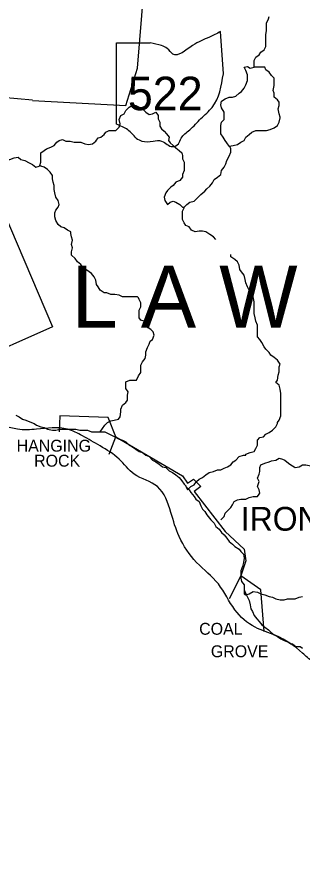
# Model space of a CAD drawing. Extents: x 0 to 34, y 0 to 22.
# Drawn here: x 6.907 to 7.373, y 14.971 to 16.352 of the extents above; entities that cross this region are included whole.
import ezdxf

# ---------------------------------------------------------------- set-up
doc = ezdxf.new("R2010")
doc.units = 0
doc.layers.add('Default', color=7, linetype='Continuous')
doc.layers.add('TR_Turning_Path1', color=7, linetype='Continuous')

msp = doc.modelspace()

# ---------------------------------------------------------------- linework, layer by layer
at = {"layer": 'Default'}
msp.add_line((7.0847, 16.207), (7.0847, 16.207), dxfattribs=at)
for points in [[(7.1038, 16.2683), (7.1256, 16.5342)], [(7.2947, 16.2697), (7.2947, 16.2765), (7.2947, 16.2806), (7.2974, 16.286), (7.3029, 16.2901), (7.3056, 16.2942), (7.3111, 16.2983), (7.3138, 16.3038), (7.3138, 16.3106), (7.3138, 16.3174), (7.3138, 16.3229), (7.3151, 16.3297), (7.3151, 16.3351), (7.3151, 16.3419), (7.3179, 16.3488), (7.3192, 16.3528)], [(7.2444, 16.2591), (7.2398, 16.3281)], [(7.0696, 16.1763), (7.0696, 16.3097), (7.1248, 16.3097)], [(7.0847, 16.207), (7.1038, 16.2683), (7.1038, 16.2683)], [(7.2538, 16.1402), (7.2497, 16.1456), (7.247, 16.1497), (7.2442, 16.1552), (7.2402, 16.1606), (7.2402, 16.1661), (7.2402, 16.1742), (7.2415, 16.1797), (7.2456, 16.1838), (7.2456, 16.1906), (7.2456, 16.1961), (7.2415, 16.2029), (7.2402, 16.2083), (7.2415, 16.2138), (7.247, 16.2179), (7.2538, 16.2206), (7.2592, 16.2206), (7.2647, 16.222), (7.2701, 16.2274), (7.2742, 16.2301), (7.2783, 16.2356), (7.2811, 16.241), (7.2838, 16.2479), (7.2838, 16.2533), (7.2838, 16.2574), (7.2811, 16.2642), (7.2783, 16.2697), (7.2838, 16.271), (7.2879, 16.2683), (7.2947, 16.2697), (7.2947, 16.2697)], [(7.337, 16.1879), (7.3356, 16.1933), (7.3342, 16.2015), (7.3356, 16.207), (7.3356, 16.2124), (7.3329, 16.2165), (7.3274, 16.2206), (7.3274, 16.2274), (7.326, 16.2315), (7.3274, 16.2397), (7.3274, 16.2451), (7.3274, 16.252), (7.3233, 16.256), (7.3192, 16.2615), (7.3138, 16.2656), (7.3124, 16.2697), (7.307, 16.2697), (7.3029, 16.2697), (7.2961, 16.2697), (7.2947, 16.2697), (7.2947, 16.2697)], [(6.8829, 16.2206), (6.872, 16.0611), (6.9647, 15.8443), (6.6948, 15.7243)], [(6.8829, 16.2206), (6.932, 16.2165), (6.932, 16.2165)], [(6.932, 16.2151), (7.0847, 16.207)], [(7.0902, 16.2042), (7.0943, 16.207), (7.1011, 16.207), (7.1065, 16.2042), (7.112, 16.2015), (7.1174, 16.1961), (7.1229, 16.192), (7.1284, 16.1933), (7.1338, 16.1961), (7.1379, 16.1906), (7.1379, 16.1851), (7.1406, 16.1797), (7.1406, 16.1729), (7.1433, 16.1688), (7.1474, 16.1647), (7.1515, 16.1606), (7.1556, 16.1552), (7.1543, 16.1497), (7.157, 16.1456), (7.1624, 16.1415), (7.1665, 16.1374), (7.172, 16.1333), (7.1761, 16.1292), (7.1774, 16.1252), (7.1774, 16.1252)], [(7.0111, 16.147), (7.0179, 16.1442), (7.0234, 16.1429), (7.0302, 16.1442), (7.0356, 16.1483), (7.0397, 16.1538), (7.0438, 16.1552), (7.0493, 16.1592), (7.052, 16.1633), (7.0575, 16.1661), (7.0629, 16.1661), (7.0684, 16.1661), (7.0738, 16.1715), (7.0752, 16.177), (7.0738, 16.1838), (7.0765, 16.1906), (7.082, 16.1933), (7.0847, 16.1988), (7.0902, 16.2042), (7.0902, 16.2042), (7.0902, 16.2042)], [(7.2538, 16.1402), (7.2606, 16.1415), (7.2674, 16.1429), (7.2729, 16.147), (7.2783, 16.1497), (7.2811, 16.1552), (7.2865, 16.1592), (7.2906, 16.1633), (7.2974, 16.1661), (7.3029, 16.1661), (7.3097, 16.1661), (7.3151, 16.1661), (7.3206, 16.1674), (7.3274, 16.1702), (7.3329, 16.1742), (7.3356, 16.1797), (7.337, 16.1865), (7.337, 16.1879)], [(6.9443, 16.1088), (6.9457, 16.1143), (6.9457, 16.1211), (6.9457, 16.1292), (6.9511, 16.1333), (6.9552, 16.1361), (6.962, 16.1388), (6.9675, 16.1415), (6.9716, 16.147), (6.9756, 16.1497), (6.9811, 16.1511), (6.9866, 16.1483), (6.9934, 16.1483), (7.0002, 16.147), (7.007, 16.147), (7.0097, 16.147), (7.0111, 16.147)], [(7.1802, 16.0406), (7.1843, 16.0447), (7.1897, 16.0488), (7.1965, 16.0502), (7.2006, 16.0543), (7.2047, 16.0584), (7.2074, 16.0611), (7.2142, 16.0665), (7.217, 16.0706), (7.2224, 16.0747), (7.2265, 16.0802), (7.2292, 16.0856), (7.2347, 16.0897), (7.2402, 16.0938), (7.2415, 16.1006), (7.2456, 16.1061), (7.2483, 16.1115), (7.2497, 16.117), (7.2538, 16.1238), (7.2565, 16.1306), (7.2565, 16.1361), (7.2552, 16.1388), (7.2538, 16.1402)], [(7.1774, 16.1252), (7.1774, 16.1197), (7.1802, 16.1143), (7.1802, 16.1061), (7.1802, 16.1006), (7.1774, 16.0938), (7.1774, 16.0897), (7.1733, 16.0843), (7.1665, 16.0815), (7.1624, 16.0761), (7.1583, 16.0733), (7.1529, 16.0679), (7.1502, 16.0638), (7.1474, 16.057), (7.1488, 16.0515), (7.1529, 16.0447), (7.157, 16.0488), (7.1624, 16.0502), (7.1665, 16.0488), (7.1733, 16.0447), (7.1774, 16.0406), (7.1802, 16.0406)], [(6.8775, 16.1183), (6.8829, 16.117), (6.8884, 16.1183), (6.8952, 16.1183), (6.902, 16.1211), (6.9088, 16.1224), (6.9129, 16.1183), (6.9197, 16.117), (6.9266, 16.1129), (6.932, 16.1102), (6.9375, 16.1061), (6.9429, 16.1074), (6.9443, 16.1088)], [(6.9947, 15.9997), (6.9893, 16.0025), (6.9838, 16.0065), (6.9784, 16.0079), (6.9743, 16.012), (6.9702, 16.0188), (6.9688, 16.0243), (6.9688, 16.0311), (6.9702, 16.0352), (6.9743, 16.0406), (6.9756, 16.0447), (6.9743, 16.0515), (6.9702, 16.057), (6.9688, 16.0638), (6.9675, 16.0693), (6.9675, 16.0761), (6.9661, 16.0815), (6.9647, 16.087), (6.9647, 16.0924), (6.9607, 16.0979), (6.9566, 16.102), (6.9511, 16.1061), (6.9457, 16.1074), (6.9443, 16.1088)], [(7.232, 15.9875), (7.2279, 15.9915), (7.2224, 15.9956), (7.2156, 15.9997), (7.2102, 16.0011), (7.2047, 16.0011), (7.1979, 15.9997), (7.1924, 16.0025), (7.1883, 16.0079), (7.1829, 16.0106), (7.1802, 16.0147), (7.1774, 16.0202), (7.1774, 16.027), (7.1774, 16.0338), (7.1802, 16.0393), (7.1802, 16.0406)], [(7.1038, 15.8934), (7.0984, 15.8934), (7.0915, 15.8934), (7.0847, 15.8934), (7.0793, 15.8934), (7.0738, 15.8961), (7.067, 15.8975), (7.0602, 15.8975), (7.0534, 15.9002), (7.0493, 15.9002), (7.0425, 15.9043), (7.0397, 15.9097), (7.037, 15.9138), (7.0356, 15.9206), (7.0329, 15.9261), (7.0288, 15.9316), (7.0247, 15.9343), (7.0193, 15.9384), (7.0138, 15.9425), (7.0111, 15.9466), (7.0056, 15.9506), (7.0016, 15.9561), (6.9961, 15.9615), (6.9961, 15.967), (6.9975, 15.9738), (6.9961, 15.9793), (6.9975, 15.9861), (6.9961, 15.9915), (6.9947, 15.997), (6.9947, 15.9997)], [(7.292, 15.8934), (7.2906, 15.9002), (7.2865, 15.9043), (7.2838, 15.9097), (7.2811, 15.9166), (7.2797, 15.922), (7.2783, 15.9288), (7.2742, 15.9343), (7.2715, 15.9384), (7.2701, 15.9452), (7.2674, 15.9506), (7.2633, 15.9547), (7.2565, 15.9588), (7.2565, 15.9629)], [(7.1284, 15.8238), (7.1311, 15.8307), (7.1297, 15.8361), (7.1256, 15.8402), (7.1215, 15.8429), (7.1174, 15.847), (7.1147, 15.8538), (7.1093, 15.8552), (7.1065, 15.8593), (7.1065, 15.8647), (7.1065, 15.8716), (7.1093, 15.877), (7.1093, 15.8838), (7.1065, 15.8893), (7.1052, 15.892), (7.1038, 15.8934)], [(7.337, 15.742), (7.3356, 15.7489), (7.3301, 15.7529), (7.3329, 15.757), (7.3342, 15.7652), (7.3356, 15.7707), (7.3356, 15.7788), (7.337, 15.7829), (7.3329, 15.7898), (7.3274, 15.7938), (7.322, 15.7979), (7.3192, 15.802), (7.3138, 15.8075), (7.3111, 15.8116), (7.307, 15.8184), (7.3042, 15.8238), (7.3001, 15.8279), (7.3001, 15.8347), (7.3001, 15.8416), (7.3001, 15.847), (7.2974, 15.8538), (7.2961, 15.8593), (7.2947, 15.8661), (7.2947, 15.8729), (7.2947, 15.8797), (7.2947, 15.8852), (7.2933, 15.8934), (7.292, 15.8934)], [(7.0874, 15.7257), (7.0874, 15.7325), (7.0888, 15.7379), (7.0847, 15.7434), (7.0847, 15.7489), (7.0847, 15.7543), (7.0915, 15.757), (7.0984, 15.757), (7.1024, 15.757), (7.1052, 15.7639), (7.1093, 15.7693), (7.1093, 15.7748), (7.1093, 15.7816), (7.112, 15.787), (7.1161, 15.7925), (7.1174, 15.7979), (7.1174, 15.8034), (7.1202, 15.8102), (7.1229, 15.8157), (7.1243, 15.8211), (7.1284, 15.8238), (7.1284, 15.8238)], [(7.3329, 15.6875), (7.3356, 15.6916), (7.3383, 15.6984), (7.3383, 15.7052), (7.3383, 15.7107), (7.3383, 15.7161), (7.3383, 15.7243), (7.3383, 15.7298), (7.3383, 15.7352), (7.337, 15.742), (7.337, 15.742)], [(7.3329, 15.6875), (7.3356, 15.6916), (7.3383, 15.6984), (7.3383, 15.7052), (7.3383, 15.7107), (7.3383, 15.7161), (7.3383, 15.7243), (7.3383, 15.7298), (7.3383, 15.7352), (7.337, 15.742), (7.337, 15.742)], [(7.037, 15.6725), (7.0425, 15.6725), (7.0465, 15.678), (7.0506, 15.6834), (7.0547, 15.6875), (7.0602, 15.6902), (7.0656, 15.6916), (7.0725, 15.693), (7.0752, 15.697), (7.0765, 15.7052), (7.0765, 15.7093), (7.0793, 15.7161), (7.0847, 15.7202), (7.0874, 15.7243), (7.0874, 15.7257)], [(6.9048, 15.6998), (6.9102, 15.697), (6.9157, 15.693), (6.9211, 15.6916), (6.9279, 15.6889), (6.9347, 15.6861), (6.9388, 15.6834), (6.9457, 15.6807), (6.9511, 15.6793), (6.9566, 15.6766), (6.9647, 15.6752), (6.9702, 15.6752), (6.977, 15.6766), (6.9838, 15.6766), (6.9893, 15.6766), (6.9961, 15.6766), (7.0029, 15.6766), (7.0097, 15.6752), (7.0166, 15.6752), (7.022, 15.6752), (7.0288, 15.6725), (7.0356, 15.6725), (7.037, 15.6725)], [(7.0575, 15.6357), (7.0684, 15.6643), (7.0561, 15.6957), (6.977, 15.6984), (6.9756, 15.6725)], [(7.2811, 15.6357), (7.2879, 15.6384), (7.2947, 15.6398), (7.2974, 15.6452), (7.3001, 15.6507), (7.3001, 15.6589), (7.3042, 15.663), (7.3097, 15.6643), (7.3138, 15.6684), (7.3192, 15.6711), (7.3247, 15.6752), (7.3301, 15.6807), (7.3329, 15.6861), (7.3329, 15.6875)], [(7.2811, 15.6357), (7.2879, 15.6384), (7.2947, 15.6398), (7.2974, 15.6452), (7.3001, 15.6507), (7.3001, 15.6589), (7.3042, 15.663), (7.3097, 15.6643), (7.3138, 15.6684), (7.3192, 15.6711), (7.3247, 15.6752), (7.3301, 15.6807), (7.3329, 15.6861), (7.3329, 15.6875)], [(7.037, 15.6725), (7.0438, 15.6725), (7.0506, 15.6725), (7.0561, 15.6698), (7.0615, 15.667), (7.067, 15.6643), (7.0738, 15.6602), (7.0793, 15.6589), (7.0847, 15.6561), (7.0902, 15.6507), (7.0943, 15.648), (7.1011, 15.6439), (7.1065, 15.6398), (7.112, 15.6384), (7.1174, 15.6343), (7.1229, 15.6316), (7.1284, 15.6261), (7.1338, 15.6234), (7.1393, 15.6193), (7.1447, 15.6152), (7.1502, 15.6139), (7.1556, 15.6084), (7.1611, 15.6057), (7.1665, 15.6016), (7.172, 15.5975), (7.1761, 15.5921), (7.1802, 15.5866), (7.1829, 15.5839), (7.1829, 15.5839), (7.1829, 15.5825)], [(7.3615, 15.6139), (7.3683, 15.6152), (7.3738, 15.618), (7.3792, 15.618), (7.3874, 15.6166), (7.3942, 15.6152), (7.3983, 15.618), (7.4038, 15.6221), (7.4092, 15.6261), (7.4133, 15.6316), (7.4188, 15.6343), (7.4256, 15.6384), (7.4283, 15.6425), (7.4351, 15.6466), (7.4378, 15.6507), (7.4419, 15.6561), (7.4447, 15.663), (7.4474, 15.667), (7.4474, 15.6684)], [(7.0684, 15.6643), (7.1774, 15.6002), (7.1856, 15.588), (7.1952, 15.5948), (7.2074, 15.5825), (7.1965, 15.5743), (7.247, 15.5089), (7.2783, 15.4803), (7.2811, 15.4612), (7.2729, 15.4366)], [(7.1829, 15.5825), (7.1856, 15.5771), (7.1911, 15.5825), (7.1965, 15.5852), (7.2006, 15.5907), (7.2047, 15.5948), (7.2102, 15.5975), (7.2156, 15.6016), (7.2211, 15.6057), (7.2279, 15.6071), (7.2347, 15.6098), (7.2402, 15.6098), (7.2456, 15.6125), (7.2511, 15.6152), (7.2565, 15.618), (7.2606, 15.6234), (7.2647, 15.6261), (7.2701, 15.6316), (7.277, 15.6343), (7.2811, 15.6343), (7.2811, 15.6357)], [(7.1829, 15.5825), (7.1856, 15.5771), (7.1911, 15.5825), (7.1965, 15.5852), (7.2006, 15.5907), (7.2047, 15.5948), (7.2102, 15.5975), (7.2156, 15.6016), (7.2211, 15.6057), (7.2279, 15.6071), (7.2347, 15.6098), (7.2402, 15.6098), (7.2456, 15.6125), (7.2511, 15.6152), (7.2565, 15.618), (7.2606, 15.6234), (7.2647, 15.6261), (7.2701, 15.6316), (7.277, 15.6343), (7.2811, 15.6343), (7.2811, 15.6357)], [(7.3042, 15.5716), (7.3029, 15.5771), (7.3001, 15.5825), (7.3029, 15.5907), (7.3001, 15.5962), (7.3029, 15.603), (7.3042, 15.6071), (7.3042, 15.6139), (7.3056, 15.618), (7.3124, 15.6207), (7.3192, 15.6234), (7.3233, 15.6248), (7.3301, 15.6261), (7.3356, 15.6289), (7.341, 15.6275), (7.3451, 15.6261), (7.3506, 15.6207), (7.3547, 15.618), (7.3601, 15.6152), (7.3615, 15.6139), (7.3615, 15.6139)], [(7.1829, 15.5825), (7.1883, 15.5771), (7.1911, 15.573), (7.1965, 15.5662), (7.1993, 15.5621), (7.2047, 15.558), (7.2074, 15.5512), (7.2102, 15.5457), (7.2142, 15.5416), (7.217, 15.5362), (7.2238, 15.528), (7.2238, 15.528)], [(7.2402, 15.528), (7.2456, 15.5334), (7.247, 15.5389), (7.2511, 15.543), (7.2565, 15.5484), (7.2592, 15.5525), (7.262, 15.558), (7.2674, 15.5607), (7.2729, 15.5621), (7.2811, 15.5621), (7.2865, 15.5648), (7.2933, 15.5662), (7.3001, 15.5662), (7.3029, 15.5702), (7.3042, 15.5716)], [(7.2238, 15.528), (7.2292, 15.5225), (7.232, 15.5171), (7.2374, 15.513), (7.2415, 15.5075), (7.2456, 15.5034), (7.2497, 15.498), (7.2538, 15.4925), (7.2592, 15.4884), (7.2633, 15.4844), (7.2701, 15.4803), (7.2729, 15.4762), (7.277, 15.4721), (7.2783, 15.4653), (7.277, 15.4584), (7.2756, 15.4516), (7.2729, 15.4448), (7.2729, 15.4394), (7.2729, 15.4325), (7.2742, 15.4271), (7.2783, 15.4216), (7.2783, 15.4135), (7.2783, 15.4135)], [(7.3111, 15.3453), (7.3056, 15.4135), (7.2729, 15.4366), (7.2538, 15.3985)], [(7.2783, 15.4135), (7.2811, 15.4066), (7.2838, 15.4012), (7.2865, 15.3957), (7.2879, 15.3889), (7.2892, 15.3821), (7.292, 15.378), (7.2947, 15.3712), (7.2988, 15.3657), (7.3029, 15.3616), (7.307, 15.3562), (7.3124, 15.3521), (7.3179, 15.348), (7.322, 15.3439), (7.3274, 15.3398), (7.3329, 15.3371), (7.3383, 15.333), (7.3438, 15.3303), (7.3506, 15.3276), (7.3547, 15.3248), (7.3574, 15.3248)], [(7.2783, 15.4135), (7.2783, 15.4066), (7.2811, 15.4053), (7.2865, 15.4066), (7.2933, 15.4107), (7.3001, 15.4094), (7.3056, 15.4066), (7.3124, 15.4053), (7.3192, 15.4025), (7.3247, 15.4012), (7.3301, 15.3985), (7.337, 15.3971), (7.3438, 15.3971), (7.3492, 15.3985), (7.3547, 15.3985), (7.3615, 15.3985), (7.3683, 15.4012), (7.3738, 15.4025)], [(7.3574, 15.3248), (7.3629, 15.3207), (7.3697, 15.3207), (7.3738, 15.318)]]:
    msp.add_lwpolyline(points, dxfattribs=at)
for points in [[(7.2398, 16.3281), (7.2214, 16.3189), (7.1938, 16.3051), (7.1616, 16.2913), (7.1524, 16.3005), (7.1432, 16.3051), (7.1248, 16.3097)], [(7.1018, 16.1533), (7.111, 16.1487), (7.1294, 16.1487), (7.1432, 16.1487), (7.1616, 16.1395), (7.1708, 16.1441), (7.1754, 16.1533), (7.1892, 16.1671), (7.2076, 16.1855), (7.226, 16.2039), (7.2444, 16.2591)], [(7.1018, 16.1533), (7.088, 16.1671), (7.0696, 16.1763)], [(8.5749, 15.7802), (8.5545, 15.7543), (8.5477, 15.7298), (8.5545, 15.6916), (8.5477, 15.6766), (8.5449, 15.6493), (8.5381, 15.6234), (8.5381, 15.603), (8.5381, 15.5743), (8.5327, 15.5525), (8.5231, 15.5334), (8.5136, 15.5075), (8.5136, 15.4762), (8.5136, 15.438), (8.5136, 15.4012), (8.5027, 15.3739), (8.4918, 15.3385), (8.4836, 15.3003), (8.4809, 15.2744), (8.474, 15.2471), (8.4591, 15.2103), (8.4427, 15.1735), (8.4277, 15.1585), (8.3963, 15.1408), (8.365, 15.1367), (8.3254, 15.1271), (8.29, 15.1271), (8.26, 15.119), (8.23, 15.1162), (8.2055, 15.1094), (8.185, 15.1094), (8.1632, 15.119), (8.1427, 15.1299), (8.1155, 15.119), (8.0923, 15.1094), (8.0718, 15.0999), (8.0459, 15.093), (8.0078, 15.0849), (7.9737, 15.074), (7.9437, 15.0671), (7.9137, 15.0562), (7.8823, 15.0426), (7.8496, 15.0303), (7.8182, 15.0208), (7.7828, 15.0017), (7.7501, 14.9881), (7.6983, 14.9785), (7.6465, 14.9717), (7.6055, 14.9717), (7.5646, 14.9785), (7.5278, 14.9935), (7.5006, 15.0208), (7.4801, 15.0344), (7.4665, 15.0671), (7.4583, 15.0944), (7.4528, 15.1367), (7.4528, 15.1612), (7.4433, 15.2008), (7.4433, 15.2226), (7.4338, 15.243), (7.4229, 15.2853), (7.3915, 15.2962), (7.3738, 15.3098), (7.3301, 15.3385), (7.2961, 15.3521), (7.2633, 15.3807), (7.2361, 15.423), (7.2006, 15.4584), (7.172, 15.5007), (7.1583, 15.5403), (7.1365, 15.5825), (7.0984, 15.603), (7.0738, 15.6275), (7.0425, 15.6493), (7.0138, 15.6657), (6.9893, 15.6766), (6.9388, 15.6766), (6.9075, 15.6766), (6.8857, 15.6807), (6.8543, 15.6766), (6.8339, 15.6766), (6.7902, 15.6807), (6.748, 15.6916), (6.7248, 15.712), (6.6948, 15.7243)]]:
    msp.add_spline(points, degree=3, dxfattribs=at)

# ---------------------------------------------------------------- texts
for s, height, p in [('522', 0.05486, (7.088, 16.1993)), ('HANGING', 0.0195, (6.9061, 15.6398)), ('ROCK', 0.0195, (6.9347, 15.6152)), ('IRONTON', 0.039, (7.2729, 15.5103)), ('COAL', 0.0195, (7.2047, 15.3398)), ('GROVE', 0.0195, (7.2238, 15.303))]:
    msp.add_text(s, height=height, dxfattribs=at).set_placement(p)
at = {"layer": 'TR_Turning_Path1'}
msp.add_text('L A W R E N C E', height=0.101489, dxfattribs=at).set_placement((6.9961, 15.8429))

doc.saveas('drawing.dxf')
